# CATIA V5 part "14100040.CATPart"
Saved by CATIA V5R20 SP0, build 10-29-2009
Part number: 14100040
Definition: NONE
Nomenclature: 14100040
Source: Unknown
Description: 14100040
Bounding box of the stored display mesh (mm): x -20 to 80, y -64 to 53.915, z -54.1 to 54.1
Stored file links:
  C:\Users\Utente\Desktop\IO LAVORO\3D X SITO CF\X SITO\PLASTICA\RF2\14100040.CATPart
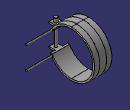
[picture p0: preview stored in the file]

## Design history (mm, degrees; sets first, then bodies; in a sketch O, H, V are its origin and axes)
Body1 "14100040" (main body)
  Solid1: solid without history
